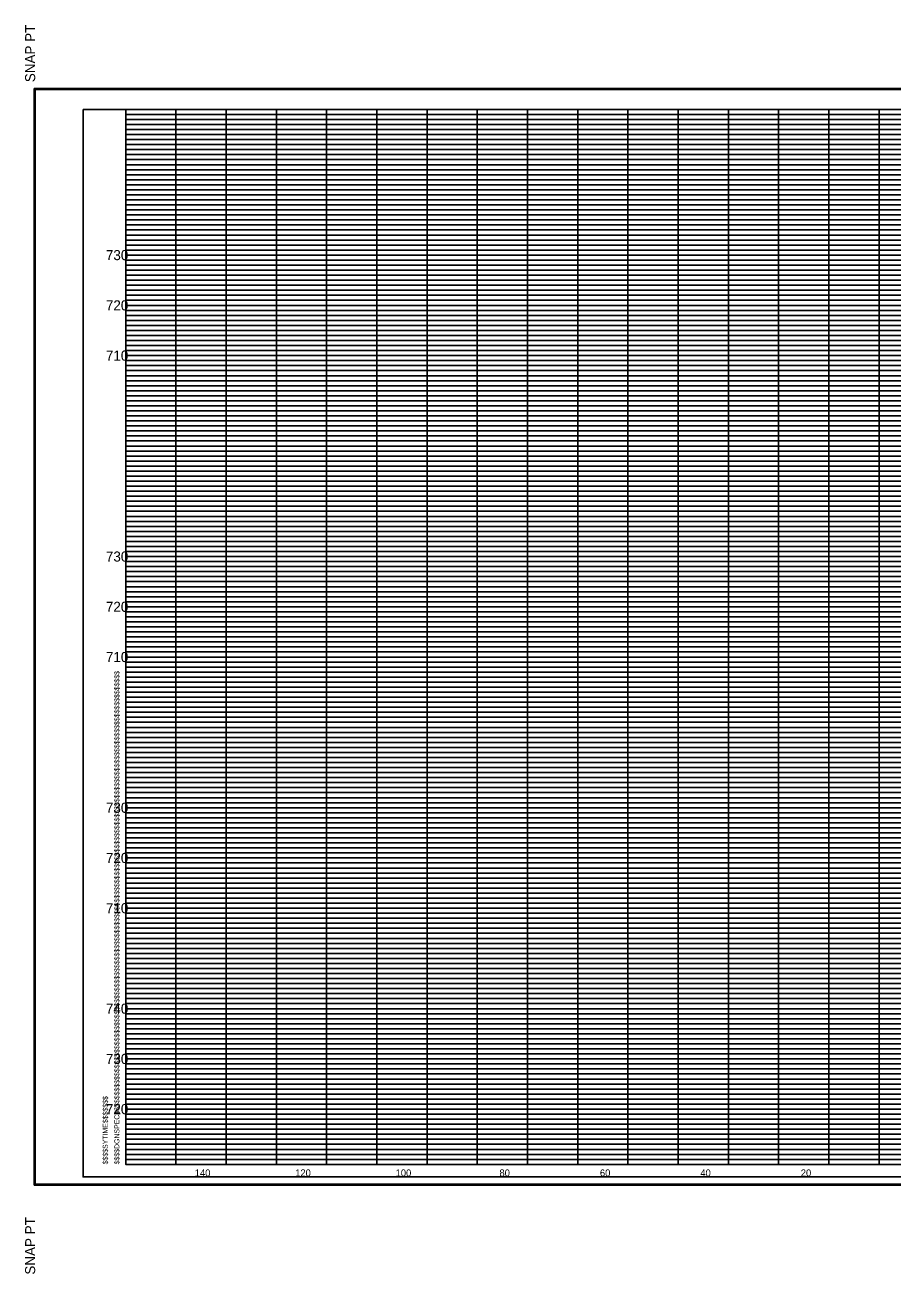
# Model space of a CAD drawing. Extents: x -200 to 1324, y -325 to 1497.
# Drawn here: x 979.9 to 1152.6, y 1248.2 to 1496.8 of the extents above; entities that cross this region are included whole.
import ezdxf

# ---------------------------------------------------------------- set-up
doc = ezdxf.new("R2010")
doc.units = 0
for name, color, linetype in [('DESIGN - SHEET - Corner Text', 7, 'Continuous'), ('DESIGN - SHEET - Light Grid', 7, 'Continuous'), ('DESIGN - SHEET - Linework', 7, 'Continuous'), ('DESIGN - SHEET - Plot Shape', 7, 'Continuous'), ('DESIGN - TYPICAL - Text', 7, 'Continuous')]:
    doc.layers.add(name, color=color, linetype=linetype)

msp = doc.modelspace()

# ---------------------------------------------------------------- linework, layer by layer
at = {"layer": 'DESIGN - SHEET - Light Grid'}
for p, q in [((1000, 1479), (1080, 1479)), ((1000, 1478), (1080, 1478)), ((1000, 1477), (1080, 1477)), ((1080, 1479), (1160, 1479)), ((1080, 1478), (1160, 1478)), ((1080, 1477), (1160, 1477)), ((1000, 1476), (1080, 1476)), ((1000, 1475), (1080, 1475)), ((1080, 1476), (1160, 1476)), ((1080, 1475), (1160, 1475)), ((1000, 1474), (1080, 1474)), ((1000, 1473), (1080, 1473)), ((1000, 1472), (1080, 1472)), ((1080, 1474), (1160, 1474)), ((1080, 1473), (1160, 1473)), ((1080, 1472), (1160, 1472)), ((1000, 1471), (1080, 1471)), ((1080, 1471), (1160, 1471)), ((1000, 1469), (1080, 1469)), ((1000, 1468), (1080, 1468)), ((1000, 1467), (1080, 1467)), ((1080, 1469), (1160, 1469)), ((1080, 1468), (1160, 1468)), ((1080, 1467), (1160, 1467)), ((1000, 1466), (1080, 1466)), ((1000, 1465), (1080, 1465)), ((1080, 1466), (1160, 1466)), ((1080, 1465), (1160, 1465)), ((1000, 1464), (1080, 1464)), ((1000, 1463), (1080, 1463)), ((1000, 1462), (1080, 1462)), ((1080, 1464), (1160, 1464)), ((1080, 1463), (1160, 1463)), ((1080, 1462), (1160, 1462)), ((1000, 1461), (1080, 1461)), ((1080, 1461), (1160, 1461)), ((1000, 1459), (1080, 1459)), ((1000, 1458), (1080, 1458)), ((1000, 1457), (1080, 1457)), ((1080, 1459), (1160, 1459)), ((1080, 1458), (1160, 1458)), ((1080, 1457), (1160, 1457)), ((1000, 1456), (1080, 1456)), ((1000, 1455), (1080, 1455)), ((1080, 1456), (1160, 1456)), ((1080, 1455), (1160, 1455)), ((1000, 1454), (1080, 1454)), ((1000, 1453), (1080, 1453)), ((1000, 1452), (1080, 1452)), ((1080, 1454), (1160, 1454)), ((1080, 1453), (1160, 1453)), ((1080, 1452), (1160, 1452)), ((1000, 1451), (1080, 1451)), ((1080, 1451), (1160, 1451)), ((1000, 1449), (1080, 1449)), ((1000, 1448), (1080, 1448)), ((1080, 1449), (1160, 1449)), ((1080, 1448), (1160, 1448)), ((1000, 1447), (1080, 1447)), ((1000, 1446), (1080, 1446)), ((1000, 1445), (1080, 1445)), ((1080, 1447), (1160, 1447)), ((1080, 1446), (1160, 1446)), ((1080, 1445), (1160, 1445)), ((1000, 1444), (1080, 1444)), ((1000, 1443), (1080, 1443)), ((1080, 1444), (1160, 1444)), ((1080, 1443), (1160, 1443)), ((1000, 1442), (1080, 1442)), ((1000, 1441), (1080, 1441)), ((1080, 1442), (1160, 1442)), ((1080, 1441), (1160, 1441)), ((1000, 1439), (1080, 1439)), ((1000, 1438), (1080, 1438)), ((1080, 1439), (1160, 1439)), ((1080, 1438), (1160, 1438)), ((1000, 1437), (1080, 1437)), ((1000, 1436), (1080, 1436)), ((1000, 1435), (1080, 1435)), ((1080, 1437), (1160, 1437)), ((1080, 1436), (1160, 1436)), ((1080, 1435), (1160, 1435)), ((1000, 1434), (1080, 1434)), ((1000, 1433), (1080, 1433)), ((1080, 1434), (1160, 1434)), ((1080, 1433), (1160, 1433)), ((1000, 1432), (1080, 1432)), ((1000, 1431), (1080, 1431)), ((1080, 1432), (1160, 1432)), ((1080, 1431), (1160, 1431)), ((1000, 1429), (1080, 1429)), ((1000, 1428), (1080, 1428)), ((1080, 1429), (1160, 1429)), ((1080, 1428), (1160, 1428)), ((1000, 1427), (1080, 1427)), ((1000, 1426), (1080, 1426)), ((1000, 1425), (1080, 1425)), ((1080, 1427), (1160, 1427)), ((1080, 1426), (1160, 1426)), ((1080, 1425), (1160, 1425)), ((1000, 1424), (1080, 1424)), ((1000, 1423), (1080, 1423)), ((1080, 1424), (1160, 1424)), ((1080, 1423), (1160, 1423)), ((1000, 1422), (1080, 1422)), ((1000, 1421), (1080, 1421)), ((1080, 1422), (1160, 1422)), ((1080, 1421), (1160, 1421)), ((1000, 1419), (1080, 1419)), ((1000, 1418), (1080, 1418)), ((1080, 1419), (1160, 1419)), ((1080, 1418), (1160, 1418)), ((1000, 1417), (1080, 1417)), ((1000, 1416), (1080, 1416)), ((1000, 1415), (1080, 1415)), ((1080, 1417), (1160, 1417)), ((1080, 1416), (1160, 1416)), ((1080, 1415), (1160, 1415)), ((1000, 1414), (1080, 1414)), ((1000, 1413), (1080, 1413)), ((1080, 1414), (1160, 1414)), ((1080, 1413), (1160, 1413)), ((1000, 1412), (1080, 1412)), ((1000, 1411), (1080, 1411)), ((1080, 1412), (1160, 1412)), ((1080, 1411), (1160, 1411)), ((1000, 1409), (1080, 1409)), ((1000, 1408), (1080, 1408)), ((1080, 1409), (1160, 1409)), ((1080, 1408), (1160, 1408)), ((1000, 1407), (1080, 1407)), ((1000, 1406), (1080, 1406)), ((1000, 1405), (1080, 1405)), ((1080, 1407), (1160, 1407)), ((1080, 1406), (1160, 1406)), ((1080, 1405), (1160, 1405)), ((1000, 1404), (1080, 1404)), ((1000, 1403), (1080, 1403)), ((1080, 1404), (1160, 1404)), ((1080, 1403), (1160, 1403)), ((1000, 1402), (1080, 1402)), ((1000, 1401), (1080, 1401)), ((1080, 1402), (1160, 1402)), ((1080, 1401), (1160, 1401)), ((1000, 1399), (1080, 1399)), ((1000, 1398), (1080, 1398)), ((1080, 1399), (1160, 1399)), ((1080, 1398), (1160, 1398)), ((1000, 1397), (1080, 1397)), ((1000, 1396), (1080, 1396)), ((1000, 1395), (1080, 1395)), ((1080, 1397), (1160, 1397)), ((1080, 1396), (1160, 1396)), ((1080, 1395), (1160, 1395)), ((1000, 1394), (1080, 1394)), ((1000, 1393), (1080, 1393)), ((1080, 1394), (1160, 1394)), ((1080, 1393), (1160, 1393)), ((1000, 1392), (1080, 1392)), ((1000, 1391), (1080, 1391)), ((1080, 1392), (1160, 1392)), ((1080, 1391), (1160, 1391)), ((1000, 1389), (1080, 1389)), ((1000, 1388), (1080, 1388)), ((1080, 1389), (1160, 1389)), ((1080, 1388), (1160, 1388)), ((1000, 1387), (1080, 1387)), ((1000, 1386), (1080, 1386)), ((1000, 1385), (1080, 1385)), ((1080, 1387), (1160, 1387)), ((1080, 1386), (1160, 1386)), ((1080, 1385), (1160, 1385)), ((1000, 1384), (1080, 1384)), ((1000, 1383), (1080, 1383)), ((1080, 1384), (1160, 1384)), ((1080, 1383), (1160, 1383)), ((1000, 1382), (1080, 1382)), ((1000, 1381), (1080, 1381)), ((1080, 1382), (1160, 1382)), ((1080, 1381), (1160, 1381)), ((1000, 1379), (1080, 1379)), ((1000, 1378), (1080, 1378)), ((1080, 1379), (1160, 1379)), ((1080, 1378), (1160, 1378)), ((1000, 1377), (1080, 1377)), ((1000, 1376), (1080, 1376)), ((1000, 1375), (1080, 1375)), ((1080, 1377), (1160, 1377)), ((1080, 1376), (1160, 1376)), ((1080, 1375), (1160, 1375)), ((1000, 1374), (1080, 1374)), ((1000, 1373), (1080, 1373)), ((1080, 1374), (1160, 1374)), ((1080, 1373), (1160, 1373)), ((1000, 1372), (1080, 1372)), ((1000, 1371), (1080, 1371)), ((1080, 1372), (1160, 1372)), ((1080, 1371), (1160, 1371)), ((1000, 1369), (1080, 1369)), ((1000, 1368), (1080, 1368)), ((1080, 1369), (1160, 1369)), ((1080, 1368), (1160, 1368)), ((1000, 1367), (1080, 1367)), ((1000, 1366), (1080, 1366)), ((1000, 1365), (1080, 1365)), ((1080, 1367), (1160, 1367)), ((1080, 1366), (1160, 1366)), ((1080, 1365), (1160, 1365)), ((1000, 1364), (1080, 1364)), ((1000, 1363), (1080, 1363)), ((1080, 1364), (1160, 1364)), ((1080, 1363), (1160, 1363)), ((1000, 1362), (1080, 1362)), ((1000, 1361), (1080, 1361)), ((1080, 1362), (1160, 1362)), ((1080, 1361), (1160, 1361)), ((1000, 1359), (1080, 1359)), ((1000, 1358), (1080, 1358)), ((1080, 1359), (1160, 1359)), ((1080, 1358), (1160, 1358)), ((1000, 1357), (1080, 1357)), ((1000, 1356), (1080, 1356)), ((1080, 1357), (1160, 1357)), ((1080, 1356), (1160, 1356)), ((1000, 1355), (1080, 1355)), ((1000, 1354), (1080, 1354)), ((1000, 1353), (1080, 1353)), ((1080, 1355), (1160, 1355)), ((1080, 1354), (1160, 1354)), ((1080, 1353), (1160, 1353)), ((1000, 1352), (1080, 1352)), ((1000, 1351), (1080, 1351)), ((1080, 1352), (1160, 1352)), ((1080, 1351), (1160, 1351)), ((1000, 1349), (1080, 1349)), ((1000, 1348), (1080, 1348)), ((1080, 1349), (1160, 1349)), ((1080, 1348), (1160, 1348)), ((1000, 1347), (1080, 1347)), ((1000, 1346), (1080, 1346)), ((1080, 1347), (1160, 1347)), ((1080, 1346), (1160, 1346)), ((1000, 1345), (1080, 1345)), ((1000, 1344), (1080, 1344)), ((1000, 1343), (1080, 1343)), ((1080, 1345), (1160, 1345)), ((1080, 1344), (1160, 1344)), ((1080, 1343), (1160, 1343)), ((1000, 1342), (1080, 1342)), ((1000, 1341), (1080, 1341)), ((1080, 1342), (1160, 1342)), ((1080, 1341), (1160, 1341)), ((1000, 1339), (1080, 1339)), ((1000, 1338), (1080, 1338)), ((1080, 1339), (1160, 1339)), ((1080, 1338), (1160, 1338)), ((1000, 1337), (1080, 1337)), ((1000, 1336), (1080, 1336)), ((1080, 1337), (1160, 1337)), ((1080, 1336), (1160, 1336)), ((1000, 1335), (1080, 1335)), ((1000, 1334), (1080, 1334)), ((1000, 1333), (1080, 1333)), ((1080, 1335), (1160, 1335)), ((1080, 1334), (1160, 1334)), ((1080, 1333), (1160, 1333)), ((1000, 1332), (1080, 1332)), ((1000, 1331), (1080, 1331)), ((1080, 1332), (1160, 1332)), ((1080, 1331), (1160, 1331)), ((1000, 1329), (1080, 1329)), ((1000, 1328), (1080, 1328)), ((1080, 1329), (1160, 1329)), ((1080, 1328), (1160, 1328)), ((1000, 1327), (1080, 1327)), ((1000, 1326), (1080, 1326)), ((1080, 1327), (1160, 1327)), ((1080, 1326), (1160, 1326)), ((1000, 1325), (1080, 1325)), ((1000, 1324), (1080, 1324)), ((1000, 1323), (1080, 1323)), ((1080, 1325), (1160, 1325)), ((1080, 1324), (1160, 1324)), ((1080, 1323), (1160, 1323)), ((1000, 1322), (1080, 1322)), ((1000, 1321), (1080, 1321)), ((1080, 1322), (1160, 1322)), ((1080, 1321), (1160, 1321)), ((1000, 1319), (1080, 1319)), ((1000, 1318), (1080, 1318)), ((1080, 1319), (1160, 1319)), ((1080, 1318), (1160, 1318)), ((1000, 1317), (1080, 1317)), ((1000, 1316), (1080, 1316)), ((1080, 1317), (1160, 1317)), ((1080, 1316), (1160, 1316)), ((1000, 1315), (1080, 1315)), ((1000, 1314), (1080, 1314)), ((1000, 1313), (1080, 1313)), ((1080, 1315), (1160, 1315)), ((1080, 1314), (1160, 1314)), ((1080, 1313), (1160, 1313)), ((1000, 1312), (1080, 1312)), ((1000, 1311), (1080, 1311)), ((1080, 1312), (1160, 1312)), ((1080, 1311), (1160, 1311)), ((1000, 1309), (1080, 1309)), ((1000, 1308), (1080, 1308)), ((1080, 1309), (1160, 1309)), ((1080, 1308), (1160, 1308)), ((1000, 1307), (1080, 1307)), ((1000, 1306), (1080, 1306)), ((1080, 1307), (1160, 1307)), ((1080, 1306), (1160, 1306)), ((1000, 1305), (1080, 1305)), ((1000, 1304), (1080, 1304)), ((1000, 1303), (1080, 1303)), ((1080, 1305), (1160, 1305)), ((1080, 1304), (1160, 1304)), ((1080, 1303), (1160, 1303)), ((1000, 1302), (1080, 1302)), ((1000, 1301), (1080, 1301)), ((1080, 1302), (1160, 1302)), ((1080, 1301), (1160, 1301)), ((1000, 1299), (1080, 1299)), ((1000, 1298), (1080, 1298)), ((1080, 1299), (1160, 1299)), ((1080, 1298), (1160, 1298)), ((1000, 1297), (1080, 1297)), ((1000, 1296), (1080, 1296)), ((1080, 1297), (1160, 1297)), ((1080, 1296), (1160, 1296)), ((1000, 1295), (1080, 1295)), ((1000, 1294), (1080, 1294)), ((1000, 1293), (1080, 1293)), ((1080, 1295), (1160, 1295)), ((1080, 1294), (1160, 1294)), ((1080, 1293), (1160, 1293)), ((1000, 1292), (1080, 1292)), ((1000, 1291), (1080, 1291)), ((1080, 1292), (1160, 1292)), ((1080, 1291), (1160, 1291)), ((1000, 1289), (1080, 1289)), ((1000, 1288), (1080, 1288)), ((1080, 1289), (1160, 1289)), ((1080, 1288), (1160, 1288)), ((1000, 1287), (1080, 1287)), ((1000, 1286), (1080, 1286)), ((1080, 1287), (1160, 1287)), ((1080, 1286), (1160, 1286)), ((1000, 1285), (1080, 1285)), ((1000, 1284), (1080, 1284)), ((1000, 1283), (1080, 1283)), ((1080, 1285), (1160, 1285)), ((1080, 1284), (1160, 1284)), ((1080, 1283), (1160, 1283)), ((1000, 1282), (1080, 1282)), ((1000, 1281), (1080, 1281)), ((1080, 1282), (1160, 1282)), ((1080, 1281), (1160, 1281)), ((1000, 1279), (1080, 1279)), ((1000, 1278), (1080, 1278)), ((1080, 1279), (1160, 1279)), ((1080, 1278), (1160, 1278)), ((1000, 1277), (1080, 1277)), ((1000, 1276), (1080, 1276)), ((1080, 1277), (1160, 1277)), ((1080, 1276), (1160, 1276)), ((1000, 1275), (1080, 1275)), ((1000, 1274), (1080, 1274)), ((1000, 1273), (1080, 1273)), ((1080, 1275), (1160, 1275)), ((1080, 1274), (1160, 1274)), ((1080, 1273), (1160, 1273)), ((1000, 1272), (1080, 1272)), ((1000, 1271), (1080, 1271)), ((1080, 1272), (1160, 1272)), ((1080, 1271), (1160, 1271))]:
    msp.add_line(p, q, dxfattribs=at)
at = {"layer": 'DESIGN - SHEET - Linework'}
for p, q in [((981.77, 1265.86), (981.77, 1484.14)), ((981.77, 1484.14), (1322.17, 1484.14)), ((1010, 1270), (1010, 1480)), ((1020, 1270), (1020, 1480)), ((1030, 1270), (1030, 1480)), ((1040, 1270), (1040, 1480)), ((1050, 1270), (1050, 1480)), ((1060, 1270), (1060, 1480)), ((1070, 1270), (1070, 1480)), ((1080, 1270), (1080, 1480)), ((1090, 1270), (1090, 1480)), ((1100, 1270), (1100, 1480)), ((1110, 1270), (1110, 1480)), ((1120, 1270), (1120, 1480)), ((1130, 1270), (1130, 1480)), ((1140, 1270), (1140, 1480)), ((1150, 1270), (1150, 1480)), ((1000, 1470), (1280, 1470)), ((1000, 1460), (1320, 1460)), ((1000, 1450), (1320, 1450)), ((1000, 1440), (1320, 1440)), ((1000, 1430), (1320, 1430)), ((1000, 1420), (1320, 1420)), ((1000, 1410), (1320, 1410)), ((1000, 1400), (1320, 1400)), ((1000, 1390), (1320, 1390)), ((1000, 1380), (1320, 1380)), ((1000, 1370), (1320, 1370)), ((1000, 1360), (1320, 1360)), ((1000, 1350), (1320, 1350)), ((1000, 1340), (1320, 1340)), ((1000, 1330), (1320, 1330)), ((1000, 1320), (1320, 1320)), ((1000, 1310), (1320, 1310)), ((1000, 1300), (1320, 1300)), ((1000, 1290), (1320, 1290)), ((1000, 1280), (1320, 1280)), ((981.77, 1265.86), (1322.17, 1265.86))]:
    msp.add_line(p, q, dxfattribs=at)
msp.add_lwpolyline([(1000, 1480), (1000, 1270), (1320, 1270), (1320, 1480), (1000, 1480)], dxfattribs=at)
at = {"layer": 'DESIGN - SHEET - Plot Shape'}
for points in [[(981.97, 1483.94), (1321.97, 1483.94), (1321.97, 1266.06), (981.97, 1266.06)], [(991.5, 1480), (1320, 1480), (1320, 1267.5), (991.5, 1267.5)]]:
    msp.add_lwpolyline(points, close=True, dxfattribs=at)

# ---------------------------------------------------------------- texts
at = {"layer": 'DESIGN - SHEET - Corner Text'}
for s, height, p in [('  SNAP PT', 2, (981.97, 1483.94)), ('$$$$DGNSPEC$$$$$$$$$$$$$$$$$$$$$$$$$$$$$$$$$$$$$$$$$$$$$$$$$$$$$$$$$$$$$$$$$$$$$$$$$$$$$$$$$$$$$$$$$$$$$$$$$$$$$$$$$$$$$$$$$$$', 1.00002, (998.74, 1270)), ('$$$$SYTIME$$$$$$$', 1, (996.42, 1270)), ('SNAP PT  ', 2, (981.97, 1248.06))]:
    msp.add_text(s, height=height, rotation=90, dxfattribs=at).set_placement(p)
at = {"layer": 'DESIGN - TYPICAL - Text'}
for s, height, p in [('     730     ', 2, (992.34, 1450)), ('     720     ', 2, (992.34, 1440)), ('     710     ', 2, (992.34, 1430)), ('     730     ', 2, (992.34, 1390)), ('     720     ', 2, (992.34, 1380)), ('     710     ', 2, (992.34, 1370)), ('     730     ', 2, (992.34, 1340)), ('     720     ', 2, (992.34, 1330)), ('     710     ', 2, (992.34, 1320)), ('     740     ', 2, (992.34, 1300)), ('     730     ', 2, (992.34, 1290)), ('     720     ', 2, (992.34, 1280)), ('     140     ', 1.4, (1011.14, 1267.6)), ('     120     ', 1.4, (1031.14, 1267.6)), ('     100     ', 1.4, (1051.14, 1267.6)), ('     80     ', 1.4, (1071.82, 1267.6)), ('     60     ', 1.4, (1091.82, 1267.6)), ('     40     ', 1.4, (1111.82, 1267.6)), ('     20     ', 1.4, (1131.82, 1267.6))]:
    msp.add_text(s, height=height, dxfattribs=at).set_placement(p)

doc.saveas('drawing.dxf')
